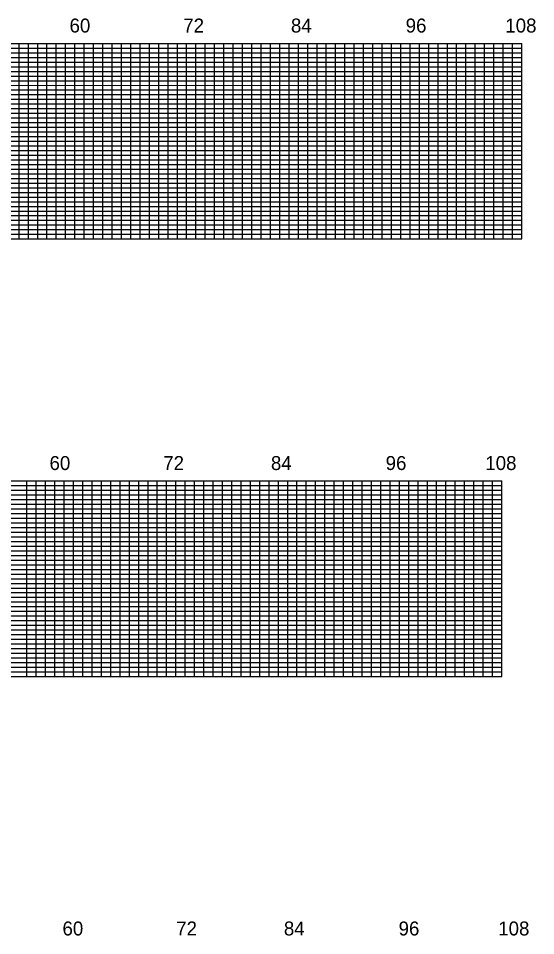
# Model space of a CAD drawing. Extents: x 1914168 to 1925341, y 720939 to 777401.
# Drawn here: x 1917154 to 1919932, y 749572 to 754499 of the extents above; entities that cross this region are included whole.
import ezdxf

# ---------------------------------------------------------------- set-up
doc = ezdxf.new("R2010")
doc.units = 0
doc.layers.add('RD_PD_WallFill', color=7, linetype='Continuous')

msp = doc.modelspace()

# ---------------------------------------------------------------- linework, layer by layer
at = {"layer": 'RD_PD_WallFill'}
for p, q in [((1914508, 754364.1), (1919858, 754364.2)), ((1917158, 753314.2), (1917158, 754364.2)), ((1917208, 753314.2), (1917208, 754364.2)), ((1917258, 753314.2), (1917258, 754364.2)), ((1917308, 753314.2), (1917308, 754364.2)), ((1917358, 753314.2), (1917358, 754364.2)), ((1917408, 753314.2), (1917408, 754364.2)), ((1917458, 753314.2), (1917458, 754364.2)), ((1917508, 753314.2), (1917508, 754364.2)), ((1917558, 753314.2), (1917558, 754364.2)), ((1917608, 753314.1), (1917608, 754364.2)), ((1917658, 753314.2), (1917658, 754364.2)), ((1917708, 753314.2), (1917708, 754364.2)), ((1917758, 753314.2), (1917758, 754364.2)), ((1917808, 753314.2), (1917808, 754364.2)), ((1917858, 753314.2), (1917858, 754364.2)), ((1917908, 753314.1), (1917908, 754364.2)), ((1917958, 753314.1), (1917958, 754364.2)), ((1918008, 753314.2), (1918008, 754364.2)), ((1918058, 753314.2), (1918058, 754364.2)), ((1918108, 753314.2), (1918108, 754364.2)), ((1918158, 753314.2), (1918158, 754364.2)), ((1918208, 753314.2), (1918208, 754364.2)), ((1918258, 753314.2), (1918258, 754364.2)), ((1918308, 753314.2), (1918308, 754364.2)), ((1918358, 753314.2), (1918358, 754364.2)), ((1918408, 753314.2), (1918408, 754364.2)), ((1918458, 753314.2), (1918458, 754364.2)), ((1918508, 753314.2), (1918508, 754364.2)), ((1918558, 753314.2), (1918558, 754364.2)), ((1918608, 753314.2), (1918608, 754364.2)), ((1918658, 753314.2), (1918658, 754364.2)), ((1918708, 753314.2), (1918708, 754364.2)), ((1918758, 753314.2), (1918758, 754364.2)), ((1918808, 753314.2), (1918808, 754364.2)), ((1918858, 753314.2), (1918858, 754364.2)), ((1918908, 753314.2), (1918908, 754364.2)), ((1918958, 753314.2), (1918958, 754364.2)), ((1919008, 753314.2), (1919008, 754364.2)), ((1919058, 753314.2), (1919058, 754364.2)), ((1919108, 753314.2), (1919108, 754364.2)), ((1919158, 753314.2), (1919158, 754364.2)), ((1919208, 753314.2), (1919208, 754364.2)), ((1919258, 753314.2), (1919258, 754364.2)), ((1919308, 753314.2), (1919308, 754364.2)), ((1919358, 753314.2), (1919358, 754364.2)), ((1919408, 753314.2), (1919408, 754364.2)), ((1919458, 753314.2), (1919458, 754364.2)), ((1919508, 753314.2), (1919508, 754364.2)), ((1919558, 753314.2), (1919558, 754364.2)), ((1919608, 753314.2), (1919608, 754364.2)), ((1919658, 753314.2), (1919658, 754364.2)), ((1919708, 753314.2), (1919708, 754364.2)), ((1919758, 753314.2), (1919758, 754364.2)), ((1919808, 753314.2), (1919808, 754364.2)), ((1919858, 753314.2), (1919858, 754364.2)), ((1914958, 754339.1), (1919858, 754339.1)), ((1914958, 754314.1), (1919858, 754314.1)), ((1914958, 754289.1), (1919858, 754289.1)), ((1914958, 754264.2), (1919858, 754264.1)), ((1914508, 754214.1), (1919858, 754214.1)), ((1914958, 754239.1), (1919858, 754239.2)), ((1914508, 754189.1), (1919858, 754189.1)), ((1914508, 754164.1), (1919858, 754164.2)), ((1914508, 754139.2), (1919858, 754139.1)), ((1914508, 754114.2), (1919858, 754114.2)), ((1914508, 754089.1), (1919858, 754089.1)), ((1914508, 754064.1), (1919858, 754064.1)), ((1914508, 754039.2), (1919858, 754039.1)), ((1914508, 754014.1), (1919858, 754014.1)), ((1914508, 753989.2), (1919858, 753989.1)), ((1914508, 753964.1), (1919858, 753964.1)), ((1914508, 753939.1), (1919858, 753939.2)), ((1914508, 753914.1), (1919858, 753914.1)), ((1914508, 753889.1), (1919858, 753889.2)), ((1914508, 753864.1), (1919858, 753864.1)), ((1914508, 753839.1), (1919858, 753839.1)), ((1914508, 753814.2), (1919858, 753814.1)), ((1914508, 753789.1), (1919858, 753789.1)), ((1914508, 753764.1), (1919858, 753764.1)), ((1914508, 753739.1), (1919858, 753739.1)), ((1914508, 753714.1), (1919858, 753714.2)), ((1914508, 753689.1), (1919858, 753689.1)), ((1914508, 753664.1), (1919858, 753664.1)), ((1914508, 753639.1), (1919858, 753639.1)), ((1914508, 753614.1), (1919858, 753614.1)), ((1914508, 753589.1), (1919858, 753589.1)), ((1914508, 753564.1), (1919858, 753564.1)), ((1914508, 753539.1), (1919858, 753539.1)), ((1914508, 753514.1), (1919858, 753514.1)), ((1914508, 753489.1), (1919858, 753489.1)), ((1914508, 753464.1), (1919858, 753464.1)), ((1914508, 753439.1), (1919858, 753439.1)), ((1914508, 753414.1), (1919858, 753414.1)), ((1914508, 753389.1), (1919858, 753389.1)), ((1914508, 753364.1), (1919858, 753364.1)), ((1914558, 753339.1), (1919858, 753339.1)), ((1914508, 753314.1), (1919858, 753314.1)), ((1914400.5, 752014.1), (1919750.5, 752014.2)), ((1914850.5, 751989.1), (1919750.5, 751989.1)), ((1917200.5, 750964.2), (1917200.5, 752014.2)), ((1917250.5, 750964.2), (1917250.5, 752014.2)), ((1917300.5, 750964.2), (1917300.5, 752014.2)), ((1917350.5, 750964.2), (1917350.5, 752014.2)), ((1917400.5, 750964.2), (1917400.5, 752014.2)), ((1917450.5, 750964.2), (1917450.5, 752014.2)), ((1917500.5, 750964.1), (1917500.5, 752014.2)), ((1917550.5, 750964.2), (1917550.5, 752014.2)), ((1917600.5, 750964.2), (1917600.5, 752014.2)), ((1917650.5, 750964.2), (1917650.5, 752014.2)), ((1917700.5, 750964.2), (1917700.5, 752014.2)), ((1917750.5, 750964.2), (1917750.5, 752014.2)), ((1917800.5, 750964.1), (1917800.5, 752014.2)), ((1917850.5, 750964.1), (1917850.5, 752014.2)), ((1917900.5, 750964.2), (1917900.5, 752014.2)), ((1917950.5, 750964.2), (1917950.5, 752014.2)), ((1918000.5, 750964.2), (1918000.5, 752014.2)), ((1918050.5, 750964.2), (1918050.5, 752014.2)), ((1918100.5, 750964.2), (1918100.5, 752014.2)), ((1918150.5, 750964.2), (1918150.5, 752014.2)), ((1918200.5, 750964.2), (1918200.5, 752014.2)), ((1918250.5, 750964.2), (1918250.5, 752014.2)), ((1918300.5, 750964.2), (1918300.5, 752014.2)), ((1918350.5, 750964.2), (1918350.5, 752014.2)), ((1918400.5, 750964.2), (1918400.5, 752014.2)), ((1918450.5, 750964.2), (1918450.5, 752014.2)), ((1918500.5, 750964.2), (1918500.5, 752014.2)), ((1918550.5, 750964.2), (1918550.5, 752014.2)), ((1918600.5, 750964.2), (1918600.5, 752014.2)), ((1918650.5, 750964.2), (1918650.5, 752014.2)), ((1918700.5, 750964.2), (1918700.5, 752014.2)), ((1918750.5, 750964.2), (1918750.5, 752014.2)), ((1918800.5, 750964.2), (1918800.5, 752014.2)), ((1918850.5, 750964.2), (1918850.5, 752014.2)), ((1918900.5, 750964.2), (1918900.5, 752014.2)), ((1918950.5, 750964.2), (1918950.5, 752014.2)), ((1919000.5, 750964.2), (1919000.5, 752014.2)), ((1919050.5, 750964.2), (1919050.5, 752014.2)), ((1919100.5, 750964.2), (1919100.5, 752014.2)), ((1919150.5, 750964.2), (1919150.5, 752014.2)), ((1919200.5, 750964.2), (1919200.5, 752014.2)), ((1919250.5, 750964.2), (1919250.5, 752014.2)), ((1919300.5, 750964.2), (1919300.5, 752014.2)), ((1919350.5, 750964.2), (1919350.5, 752014.2)), ((1919400.5, 750964.2), (1919400.5, 752014.2)), ((1919450.5, 750964.2), (1919450.5, 752014.2)), ((1919500.5, 750964.2), (1919500.5, 752014.2)), ((1919550.5, 750964.2), (1919550.5, 752014.2)), ((1919600.5, 750964.2), (1919600.5, 752014.2)), ((1919650.5, 750964.2), (1919650.5, 752014.2)), ((1919700.5, 750964.2), (1919700.5, 752014.2)), ((1919750.5, 750964.2), (1919750.5, 752014.2)), ((1914850.5, 751964.1), (1919750.5, 751964.1)), ((1914850.5, 751939.1), (1919750.5, 751939.1)), ((1914850.5, 751914.2), (1919750.5, 751914.1)), ((1914850.5, 751889.1), (1919750.5, 751889.2)), ((1914400.5, 751864.1), (1919750.5, 751864.1)), ((1914400.5, 751839.1), (1919750.5, 751839.1)), ((1914400.5, 751814.1), (1919750.5, 751814.2)), ((1914400.5, 751789.2), (1919750.5, 751789.1)), ((1914400.5, 751764.2), (1919750.5, 751764.2)), ((1914400.5, 751739.1), (1919750.5, 751739.1)), ((1914400.5, 751714.1), (1919750.5, 751714.1)), ((1914400.5, 751689.2), (1919750.5, 751689.1)), ((1914400.5, 751664.1), (1919750.5, 751664.1)), ((1914400.5, 751639.2), (1919750.5, 751639.1)), ((1914400.5, 751614.1), (1919750.5, 751614.1)), ((1914400.5, 751589.1), (1919750.5, 751589.2)), ((1914400.5, 751564.1), (1919750.5, 751564.1)), ((1914400.5, 751539.1), (1919750.5, 751539.2)), ((1914400.5, 751514.1), (1919750.5, 751514.1)), ((1914400.5, 751489.1), (1919750.5, 751489.1)), ((1914400.5, 751464.2), (1919750.5, 751464.1)), ((1914400.5, 751439.1), (1919750.5, 751439.1)), ((1914400.5, 751414.1), (1919750.5, 751414.1)), ((1914400.5, 751389.1), (1919750.5, 751389.1)), ((1914400.5, 751364.1), (1919750.5, 751364.2)), ((1914400.5, 751339.1), (1919750.5, 751339.1)), ((1914400.5, 751314.1), (1919750.5, 751314.1)), ((1914400.5, 751289.1), (1919750.5, 751289.1)), ((1914400.5, 751264.1), (1919750.5, 751264.1)), ((1914400.5, 751239.1), (1919750.5, 751239.1)), ((1914400.5, 751214.1), (1919750.5, 751214.1)), ((1914400.5, 751189.1), (1919750.5, 751189.1)), ((1914400.5, 751164.1), (1919750.5, 751164.1)), ((1914400.5, 751139.1), (1919750.5, 751139.1)), ((1914400.5, 751114.1), (1919750.5, 751114.1)), ((1914400.5, 751089.1), (1919750.5, 751089.1)), ((1914400.5, 751064.1), (1919750.5, 751064.1)), ((1914400.5, 751039.1), (1919750.5, 751039.1)), ((1914400.5, 751014.1), (1919750.5, 751014.1)), ((1914400.5, 750964.1), (1919750.5, 750964.1)), ((1914450.5, 750989.1), (1919750.5, 750989.1))]:
    msp.add_line(p, q, dxfattribs=at)

# ---------------------------------------------------------------- texts
for s, p in [('60', (1917429.1, 754422.8)), ('72', (1918039.8, 754422.8)), ('84', (1918618.1, 754422.8)), ('96', (1919234.1, 754422.8)), ('108', (1919769.2, 754422.8)), ('60', (1917321.6, 752072.8)), ('72', (1917932.3, 752072.8)), ('84', (1918510.6, 752072.8)), ('96', (1919126.6, 752072.8)), ('108', (1919661.7, 752072.8)), ('60', (1917391.2, 749572.8)), ('72', (1918001.9, 749572.8)), ('84', (1918580.1, 749572.8)), ('96', (1919196.2, 749572.8)), ('108', (1919731.2, 749572.8))]:
    msp.add_text(s, height=75, dxfattribs=at).set_placement(p)

doc.saveas('drawing.dxf')
